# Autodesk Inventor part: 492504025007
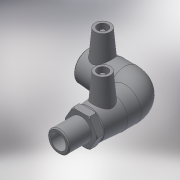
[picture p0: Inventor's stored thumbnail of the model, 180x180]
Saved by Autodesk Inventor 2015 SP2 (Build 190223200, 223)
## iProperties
Created: 2017-06
Part Number: 492504025007
Material: Generic
Description: PLASSON 90° ELBOW MALE TRANSITION 25-3/4"
Document SubType Name: Modeling
Designer: KIM
Mass: 74.2816 g
Surface Area: 274.187 cm^2
Volume: 74.2816 cm^3
Density: 1 g/cm^3
Appearance: Default
Author: KIM
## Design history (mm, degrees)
derived "492504.ipt"
feature "Solid1::492504.ipt"
tag "TaggingFeature1"
body "Solid1"
other parameters: "d2" = 36, "d4" = 22, "d5" = 32.4, "d8" = 168 deg, "d10" = 14.8, "d11" = 4.93333, "d29" = 38, "d30" = 15, "d31" = 36.3, "d34" = 5 deg, "d41" = 4, "d42" = 14, "d43" = 0, "d48" = 51.3, "d49" = 25, "d50" = 21.25, "d51" = 14.8, "d52" = 37, "d54" = 90 deg, "d57" = 25, "d58" = 37, "d59" = 0, "d61" = 90 deg, "d86" = 3, "d87" = 0, "d93" = 0.1, "d94" = 7.25, "d95" = 26.441, "d96" = 18.5087, "d97" = 19, "d98" = 29, "d99" = 36, "d100" = 26.1, "d102" = 1.25, "d106" = 0, "d_" = 25, "L_" = 95, "L_1" = 37, "D_" = 19, "A_" = 38, "d_2" = 12, "L_2" = 29, "D_1" = 36, "R_" = 26.441
